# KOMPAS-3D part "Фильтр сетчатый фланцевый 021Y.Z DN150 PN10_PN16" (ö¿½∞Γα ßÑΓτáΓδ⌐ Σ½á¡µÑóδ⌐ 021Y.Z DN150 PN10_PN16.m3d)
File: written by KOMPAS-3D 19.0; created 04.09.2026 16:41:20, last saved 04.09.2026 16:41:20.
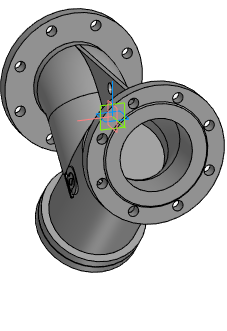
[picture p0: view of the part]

Document properties: Автор: Энергия; Полное имя файла: Z:\3.Личные\sachek\Dendor\_3D для проектировщиков\8.1 Фильтр сетчатый 021Y.Z\021Y.Z_STP\Фильтр сетчатый фланцевый 021Y.Z DN150 PN10_PN16.m3d

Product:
- Part/product: Фильтр сетчатый фланцевый 021Y.Z DN150 PN10_PN16

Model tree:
1. Операция без истории:1  (labels: Фильтр сетчатый фланцевый 021Y.Z DN150 PN10_PN16)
